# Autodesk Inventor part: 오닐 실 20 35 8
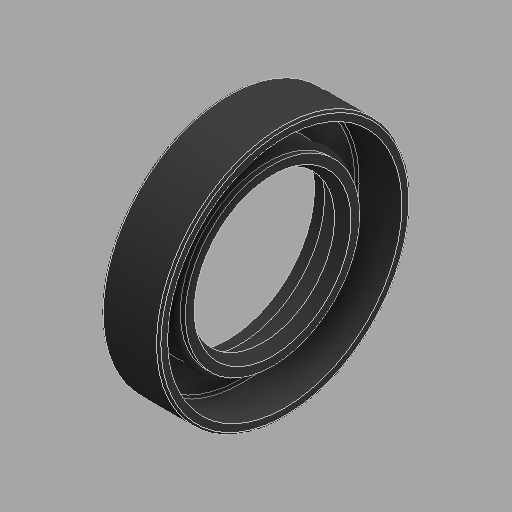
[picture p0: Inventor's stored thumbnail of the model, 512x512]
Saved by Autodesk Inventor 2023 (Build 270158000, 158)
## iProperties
Created: 2025-09
Part Number: 오닐 실 20 35 8
Material: 고무
Description: 오일-실
Document SubType Name: Modeling
Designer: home
Density: 0.93 g/cm^3
Appearance: 기본값
Author: jhkim
Sending System: Autodesk Inventor 2026
Preprocessor: ST-DEVELOPER v20.1
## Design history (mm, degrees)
feature "Solid1"
node "솔리드1"
